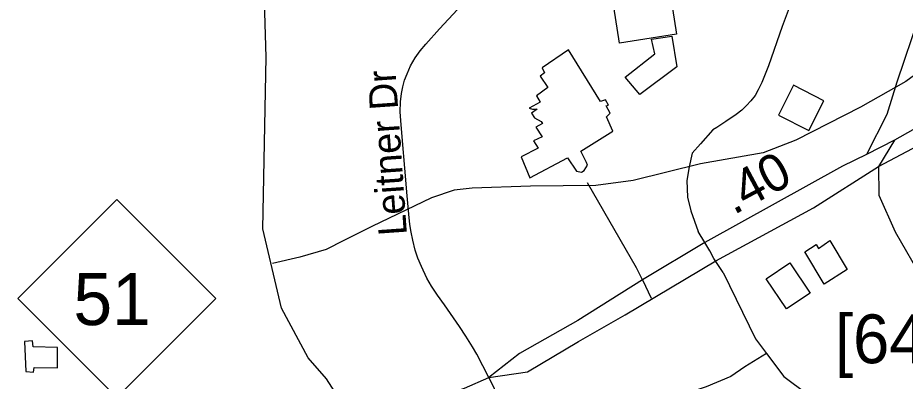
# Model space of a CAD drawing. Extents: x 1383679 to 1536984, y 460658 to 651027.
# Drawn here: x 1435824 to 1438807, y 491361 to 492583 of the extents above; entities that cross this region are included whole.
import ezdxf

# ---------------------------------------------------------------- set-up
doc = ezdxf.new("R2010")
doc.units = 0
for name, color, linetype in [('Exist Cultural Warehouse Building Footprint', 7, 'Continuous'), ('Exist Hydrographic Creek Single Shore', 7, 'Continuous'), ('Exist Hydrographic Misc Water Feature', 7, 'Continuous'), ('Exist Road Non-System Type 51', 7, 'Continuous'), ('Exist Road Non-System Type 51 Label', 7, 'Continuous'), ('Exist Road Primary Interstate Ramp 1 Lane Attributed', 7, 'Continuous'), ('Exist Road Primary Interstate Shield CELL', 7, 'Continuous'), ('Exist Road Primary NC Attributed', 7, 'Continuous'), ('Exist Road Primary NC Shield CELL', 7, 'Continuous'), ('Exist Road Primary NC Shield Number Label', 7, 'Continuous'), ('Exist Road Primary NC UnDivided 4 Lane Attributed', 7, 'Continuous'), ('Exist Road Secondary Mileage Hundredths English Label', 7, 'Continuous'), ('Exist Road Secondary Type 51 Attributed', 7, 'Continuous')]:
    doc.layers.add(name, color=color, linetype=linetype)

msp = doc.modelspace()

# ---------------------------------------------------------------- linework, layer by layer
at = {"layer": 'Exist Cultural Warehouse Building Footprint'}
for points in [[(1437808.8, 492743.8), (1438000.7, 492773.6), (1438038.8, 492528.1), (1437846.9, 492498.3), (1437808.8, 492743.8)], [(1437954.7, 492510.8), (1438023.2, 492521.7), (1438039.1, 492418.1), (1437914.8, 492325.3), (1437865.4, 492384), (1437965.8, 492461.4), (1437954.7, 492510.8)], [(1437675.7, 492475.3), (1437586.4, 492415), (1437594.4, 492398), (1437580, 492387.1), (1437605.6, 492348.5), (1437567.3, 492320.6), (1437580, 492299), (1437543.4, 492278.9), (1437554.5, 492275.8), (1437570.5, 492275.8), (1437551.4, 492261.9), (1437560.9, 492246.4), (1437583.2, 492234), (1437588, 492227.8), (1437565.7, 492215.5), (1437586.4, 492183), (1437557.7, 492169.1), (1437573.7, 492144.3), (1437516.3, 492115), (1437545, 492045.4), (1437672.5, 492111.9), (1437702.8, 492067), (1437718.7, 492063.9), (1437728.3, 492070.1), (1437739.5, 492087.1), (1437736.3, 492096.4), (1437717.1, 492135.1), (1437823.9, 492201.6), (1437803.2, 492249.5), (1437816, 492261.9), (1437801.6, 492286.6), (1437809.6, 492289.7), (1437800, 492306.7), (1437782.5, 492302.1), (1437675.7, 492475.3)], [(1438431.7, 492356.1), (1438380.9, 492255.5), (1438483.5, 492203.7), (1438534.3, 492304.4), (1438431.7, 492356.1)], [(1438470.1, 491796.5), (1438508.4, 491820.7), (1438516.1, 491807.6), (1438554.4, 491833.7), (1438611.9, 491737), (1438535.2, 491686.8), (1438470.1, 491796.5)], [(1438339.7, 491705.4), (1438419.2, 491758.6), (1438487.3, 491657), (1438407.8, 491603.8), (1438339.7, 491705.4)], [(1435846.9, 491494.5), (1435850.5, 491393.8), (1435877.1, 491391.4), (1435879.5, 491406.6), (1435958, 491405.5), (1435958, 491474.6), (1435875.9, 491476.9), (1435873.5, 491496.8), (1435846.9, 491494.5)]]:
    msp.add_lwpolyline(points, dxfattribs=at)
at = {"layer": 'Exist Hydrographic Creek Single Shore'}
msp.add_lwpolyline([(1436155, 489208.7), (1436490.1, 489158.1), (1436708.7, 489039.4), (1436960.7, 489090.9), (1437136.9, 489273.5), (1437431.2, 490134.7), (1437439.2, 490498.9), (1437318.2, 490744.3), (1437088.9, 491016.6), (1437028, 491046.2), (1436940.2, 491246.6), (1436861.6, 491368.4), (1436799.9, 491439.4), (1436710.2, 491606.6), (1436648.2, 491873.8), (1436659.2, 492451.2), (1436644.2, 492940.6), (1436679.2, 493008.8), (1436857.2, 493172.6), (1437116.3, 493190.4), (1437191.2, 493221.7), (1437640.4, 493919.4)], dxfattribs=at)
at = {"layer": 'Exist Hydrographic Misc Water Feature'}
msp.add_lwpolyline([(1439111.5, 492580.7), (1438979.7, 492493.1), (1438809, 492368.5), (1438657.4, 492282.9), (1438439.1, 492171.6), (1438330.3, 492129.5), (1438119.5, 492091.9), (1437892.3, 492035.8), (1437767.8, 492018.6), (1437547.7, 492016.4), (1437351.4, 492010.5), (1437291.4, 492003.5), (1437214.8, 491977.2), (1437014.7, 491881.1), (1436919.8, 491834.6), (1436861.2, 491803.7), (1436772.7, 491777.6), (1436680.2, 491757.3)], dxfattribs=at)
at = {"layer": 'Exist Road Non-System Type 51'}
for p, q in [((1437903.8, 491742.3), (1437738.9, 492028.2)), ((1438133.7, 491827.6), (1438111.3, 491864.5)), ((1438150.7, 491799.6), (1438133.7, 491827.6)), ((1438164.5, 491773.1), (1438150.7, 491799.6)), ((1438195.4, 491726.2), (1438164.5, 491773.1)), ((1437924.4, 491702.1), (1437903.8, 491742.3)), ((1437924.4, 491702.1), (1437953.5, 491640.1))]:
    msp.add_line(p, q, dxfattribs=at)
for points in [[(1438490.8, 492822.4), (1438489.6, 492819.3), (1438444.4, 492689.2), (1438394, 492553.4), (1438347.2, 492421.6), (1438325, 492365.6), (1438313.5, 492341.2), (1438302.4, 492321.9), (1438288.7, 492304.3), (1438273.9, 492287.9), (1438257.9, 492273), (1438238.5, 492257.5), (1438203.9, 492234), (1438174.4, 492214.5), (1438160.9, 492205.9), (1438118.8, 492159.2), (1438091.6, 492127.6), (1438080.7, 492081.8), (1438073.4, 492036.1), (1438075.2, 491979.8), (1438086.1, 491934), (1438111.6, 491864.7)], [(1437407.3, 491373.6), (1437367.2, 491451.7), (1437352.8, 491476.6), (1437330.6, 491511.9), (1437308.9, 491545.2), (1437289.2, 491573.9), (1437258, 491617.8), (1437235, 491649.9), (1437215.1, 491680.3), (1437199.4, 491707.6), (1437180.8, 491746.4), (1437169.2, 491775.1), (1437159.9, 491801.7), (1437151.6, 491834.9), (1437146.4, 491862.4), (1437142.5, 491887.7), (1437138.9, 491922.9), (1437133.3, 491984), (1437124.7, 492077.8), (1437117.5, 492169.7), (1437111.6, 492237.4), (1437110, 492267.3), (1437110.5, 492300.5), (1437114, 492328.8), (1437118.6, 492350.8), (1437124.5, 492373.4), (1437132.8, 492395.2), (1437144.7, 492421.3), (1437160.4, 492449), (1437177.2, 492472.3), (1437196.3, 492494.3), (1437241.8, 492545.8), (1437302.4, 492610.9)], [(1438195.4, 491726.2), (1438304.6, 491503.8), (1438340.9, 491454.5)], [(1438340.9, 491454.5), (1438268.4, 491408.8), (1438221.2, 491377.1), (1438137.8, 491341.9), (1438054.4, 491313.8), (1437945.6, 491257.5), (1437883.9, 491218.8), (1437844, 491180.1), (1437815, 491155.4), (1437804.1, 491109.7), (1437796.9, 491039.3), (1437804.1, 490863.3), (1437883.9, 490578.3)], [(1438340.9, 491454.5), (1438398.9, 491377.1), (1438478.7, 491317.3), (1438580.3, 491271.5), (1438692.7, 491243.4), (1438808.7, 491222.3)]]:
    msp.add_lwpolyline(points, dxfattribs=at)
at = {"layer": 'Exist Road Primary Interstate Ramp 1 Lane Attributed'}
for points in [[(1439015.5, 494073.2), (1439060.7, 493608.6), (1439060.7, 493460.8), (1439057.7, 493337.1), (1439018.6, 493182.1), (1438929.5, 492811.6), (1438779.4, 492366.7), (1438746.1, 492258.3), (1438677.7, 492123.7)], [(1438771.6, 492171.9), (1438717, 492082.5)], [(1438717, 492082.5), (1438718.7, 491986.4), (1438773.3, 491863.8), (1438866.4, 491701.8), (1439037.6, 491379.4), (1439200.1, 491108.4), (1439326.9, 490892.3), (1439456.5, 490624.6), (1439597, 490175.3)]]:
    msp.add_lwpolyline(points, dxfattribs=at)
at = {"layer": 'Exist Road Primary NC Attributed'}
msp.add_lwpolyline([(1436940.2, 491246.6), (1437053, 491265.1), (1437193.9, 491294.1), (1437325.2, 491337.8), (1437407.3, 491373.6)], dxfattribs=at)
at = {"layer": 'Exist Road Primary NC Shield CELL'}
msp.add_lwpolyline([(1435823.8, 491639.3), (1436156.8, 491972.3), (1436489.8, 491639.3), (1436156.8, 491306.3)], close=True, dxfattribs=at)
at = {"layer": 'Exist Road Primary NC UnDivided 4 Lane Attributed'}
for points in [[(1439254.6, 492440.7), (1439084.4, 492349.5), (1439047.4, 492329.7), (1438832.7, 492206.7), (1438771.6, 492171.9)], [(1438717, 492082.5), (1438984, 492223.7), (1439063.5, 492262.8)], [(1438771.6, 492171.9), (1438677.7, 492123.7)], [(1438677.7, 492123.7), (1438596.5, 492084.2), (1438133.7, 491827.6), (1437924.4, 491702.1), (1437706.8, 491564.6), (1437510.1, 491454.1), (1437407.3, 491373.6)], [(1437407.3, 491373.6), (1437537, 491392.8), (1437709.2, 491494.8), (1437865.4, 491584.5), (1438171, 491766.2), (1438498.8, 491944.1), (1438717, 492082.5)]]:
    msp.add_lwpolyline(points, dxfattribs=at)
at = {"layer": 'Exist Road Secondary Type 51 Attributed'}
msp.add_lwpolyline([(1437407.3, 491373.6), (1437479.6, 491225.8), (1437508.6, 491157.2), (1437526.7, 491100.9), (1437547.6, 490959.2), (1437578.4, 490799.1), (1437598.3, 490700.6), (1437627.3, 490602), (1437646.6, 490547.5), (1437673.6, 490471), (1437776, 490155.1), (1437874.9, 489835.8), (1437932.9, 489651), (1437967, 489467.7), (1437972.8, 489436.3), (1437999.1, 489256), (1438010, 489062.4), (1438016.3, 488850.4)], dxfattribs=at)

# ---------------------------------------------------------------- texts
at = {"layer": 'Exist Road Non-System Type 51 Label'}
msp.add_text('Leitner Dr', height=95, rotation=93.9906, dxfattribs=at).set_placement((1437132.4, 491853.6))
at = {"layer": 'Exist Road Primary Interstate Shield CELL'}
msp.add_text('[64]', height=164.04, dxfattribs=at).set_placement((1438571, 491421.4))
at = {"layer": 'Exist Road Primary NC Shield Number Label'}
msp.add_text('51', height=175, dxfattribs=at).set_placement((1436011, 491549.6))
at = {"layer": 'Exist Road Secondary Mileage Hundredths English Label'}
msp.add_text('.40', height=125, rotation=28.1858, dxfattribs=at).set_placement((1438230.7, 491918.9))

doc.saveas('drawing.dxf')
